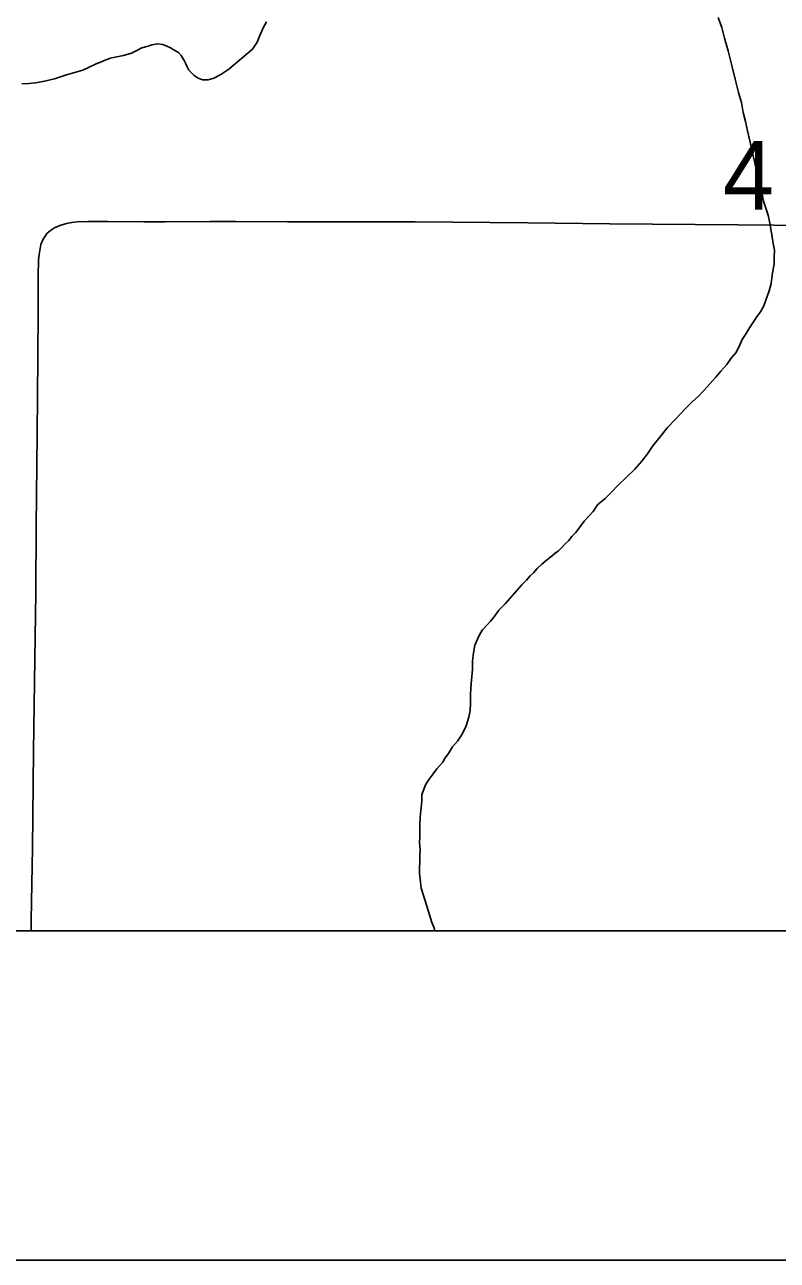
# Model space of a CAD drawing. Extents: x 2.4 to 73.1, y 4.5 to 25.6.
# Drawn here: x 44.0076 to 44.236, y 18.0051 to 18.3802 of the extents above; entities that cross this region are included whole.
import ezdxf

# ---------------------------------------------------------------- set-up
doc = ezdxf.new("R2010")
doc.units = 0
for name, color, linetype in [('GM_X_County_Road', 7, 'Continuous'), ('GM_X_Interchange_Ramps', 7, 'Continuous'), ('GM_X_Minor_River', 7, 'Continuous'), ('GM_X_Section_Text', 7, 'Continuous'), ('GM_X_US_Shield', 7, 'Continuous'), ('SH_Cut_Line', 7, 'Continuous'), ('SH_Data', 7, 'Continuous')]:
    doc.layers.add(name, color=color, linetype=linetype)

msp = doc.modelspace()

# ---------------------------------------------------------------- linework, layer by layer
at = {"layer": 'GM_X_County_Road'}
for points in [[(44.01442, 18.31698), (44.01549, 18.31775), (44.01663, 18.31851), (44.01832, 18.31928), (44.0203, 18.31986), (44.02187, 18.3202), (44.02346, 18.32037), (44.02673, 18.32051), (44.03281, 18.32048), (44.04379, 18.32037), (44.05021, 18.32038), (44.06391, 18.32047), (44.07167, 18.32047), (44.08739, 18.32033), (44.12607, 18.32037), (44.16027, 18.3201), (44.18513, 18.3198), (44.22399, 18.31949), (44.25662, 18.31916)], [(44.00955, 18.10511), (44.00957, 18.1085), (44.00995, 18.13023), (44.01028, 18.15972), (44.01067, 18.18765), (44.01095, 18.20782), (44.01111, 18.228), (44.01143, 18.25594), (44.01162, 18.27922), (44.0117, 18.29318), (44.01173, 18.30406), (44.01182, 18.30879), (44.01197, 18.31048), (44.01251, 18.31346), (44.01319, 18.31507), (44.0138, 18.31607), (44.01442, 18.31698)]]:
    msp.add_lwpolyline(points, dxfattribs=at)
at = {"layer": 'GM_X_Interchange_Ramps'}
msp.add_lwpolyline([(42.9588, 18.10511), (46.01084, 18.10511)], dxfattribs=at)
at = {"layer": 'GM_X_Minor_River'}
for points in [[(44.05432, 18.37183), (44.05506, 18.37087), (44.05597, 18.36933), (44.05652, 18.36837), (44.05688, 18.36741), (44.05743, 18.36645), (44.05891, 18.36489), (44.06004, 18.36411), (44.06154, 18.3635), (44.06325, 18.36347), (44.06498, 18.364), (44.06709, 18.36509), (44.0696, 18.36674), (44.07677, 18.37285), (44.07815, 18.37491), (44.07896, 18.37698), (44.07996, 18.37923), (44.08095, 18.38111)], [(44.14154, 18.1674), (44.14195, 18.16872), (44.14236, 18.17004), (44.14278, 18.17193), (44.14283, 18.17421), (44.14289, 18.17667), (44.14294, 18.17895), (44.14318, 18.18123), (44.14344, 18.18445), (44.1435, 18.18711), (44.14375, 18.18957), (44.14418, 18.19184), (44.14498, 18.19372), (44.14578, 18.19541), (44.14656, 18.19654), (44.14793, 18.19802), (44.1489, 18.19914), (44.15007, 18.20045), (44.15145, 18.2025), (44.15339, 18.20436), (44.15847, 18.21013), (44.15983, 18.21162), (44.161, 18.21293), (44.16197, 18.21385), (44.16314, 18.21516), (44.1645, 18.21646), (44.16586, 18.21756), (44.16721, 18.21867), (44.16857, 18.21978), (44.16954, 18.22052), (44.17051, 18.22145), (44.17148, 18.22257), (44.17264, 18.22349), (44.17362, 18.2248), (44.17479, 18.2261), (44.17597, 18.22759), (44.17734, 18.22946), (44.17871, 18.23095), (44.18007, 18.23244), (44.18145, 18.2345), (44.18377, 18.23635), (44.18552, 18.23821), (44.18766, 18.24044), (44.19019, 18.24285), (44.19271, 18.24526), (44.19486, 18.24768), (44.19662, 18.24992), (44.1982, 18.25236), (44.20035, 18.25497), (44.20269, 18.25795), (44.20522, 18.26056), (44.20815, 18.26372), (44.21009, 18.26576), (44.21203, 18.26743), (44.21378, 18.26929), (44.21554, 18.27115), (44.2173, 18.2732), (44.21886, 18.27506), (44.22062, 18.27711), (44.22199, 18.27898), (44.22336, 18.28066), (44.22435, 18.28254), (44.22535, 18.28461), (44.22653, 18.28648), (44.22752, 18.28817), (44.2287, 18.29004), (44.22988, 18.29172), (44.23086, 18.29303), (44.23185, 18.29491), (44.23347, 18.29943), (44.23409, 18.30169), (44.23455, 18.30491), (44.23499, 18.30756), (44.23503, 18.30965), (44.23508, 18.31174), (44.23475, 18.31383), (44.23441, 18.31574), (44.23407, 18.31765), (44.23374, 18.31994), (44.23323, 18.32242), (44.23252, 18.32452), (44.2318, 18.32663), (44.23112, 18.32987), (44.23023, 18.33255), (44.22972, 18.33541), (44.22903, 18.33865), (44.22834, 18.34171), (44.22765, 18.34495), (44.22696, 18.34801), (44.22627, 18.35087), (44.22557, 18.35355), (44.22506, 18.3566), (44.22418, 18.35966), (44.22331, 18.36329), (44.22209, 18.36825), (44.22105, 18.37226), (44.21999, 18.37609), (44.21911, 18.37933), (44.21804, 18.3824)], [(44.00677, 18.36227), (44.00886, 18.36241), (44.01096, 18.36255), (44.01363, 18.36306), (44.01669, 18.36375), (44.02033, 18.365), (44.0253, 18.36641), (44.02914, 18.36822), (44.03356, 18.37002), (44.03757, 18.37088), (44.04005, 18.37159), (44.0414, 18.37232), (44.04313, 18.37323), (44.04505, 18.37375), (44.04619, 18.37411), (44.04791, 18.37445), (44.04943, 18.37422), (44.05056, 18.37382), (44.05188, 18.37322), (44.05319, 18.37243), (44.05432, 18.37183)], [(44.13209, 18.10511), (44.1318, 18.10627), (44.13108, 18.10799), (44.13055, 18.10971), (44.12859, 18.11584), (44.12788, 18.11813), (44.12756, 18.1208), (44.12741, 18.12251), (44.12745, 18.12422), (44.12749, 18.12593), (44.12753, 18.12783), (44.12758, 18.12991), (44.12743, 18.13182), (44.12747, 18.13353), (44.12751, 18.13542), (44.12755, 18.13732), (44.1276, 18.1396), (44.12784, 18.14169), (44.1281, 18.14453), (44.12814, 18.14643), (44.12875, 18.14812), (44.12935, 18.14963), (44.13034, 18.15113), (44.13151, 18.15281), (44.13269, 18.1543), (44.13347, 18.15523), (44.13445, 18.15635), (44.13524, 18.15766), (44.13621, 18.15897), (44.1374, 18.16103), (44.13896, 18.16271), (44.14014, 18.16458), (44.14094, 18.16608), (44.14154, 18.1674)]]:
    msp.add_lwpolyline(points, dxfattribs=at)
at = {"layer": 'GM_X_US_Shield'}
msp.add_lwpolyline([(43.96998, 18.10511), (44.47912, 18.10511), (44.48579, 18.59368), (44.00623, 18.5965), (43.97458, 18.59666)], close=True, dxfattribs=at)
at = {"layer": 'SH_Cut_Line'}
msp.add_lwpolyline([(41.95853, 21.67404), (41.95853, 18.10511), (48.75853, 18.10511), (48.75853, 20.021)], dxfattribs=at)
at = {"layer": 'SH_Data'}
for p, q in [((41.95853, 18.10511), (48.75853, 18.10511)), ((41.85853, 18.00511), (48.85853, 18.00511))]:
    msp.add_line(p, q, dxfattribs=at)

# ---------------------------------------------------------------- texts
at = {"layer": 'GM_X_Section_Text'}
msp.add_text('4', height=0.02093, rotation=0, dxfattribs=at).set_placement((44.21943, 18.32403))

doc.saveas('drawing.dxf')
